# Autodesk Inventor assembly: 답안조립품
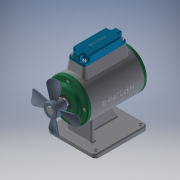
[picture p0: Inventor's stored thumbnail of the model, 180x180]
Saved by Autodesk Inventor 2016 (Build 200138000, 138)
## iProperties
Created: 2019-07
Part Number: 답안조립품
Material: 일반
Document SubType Name: Assembly
Designer: 602-01
Mass: 3420.4 g
Surface Area: 2825.58 cm^2
Volume: 1021.29 cm^3
Density: 3.34909 g/cm^3
Author: 602-01
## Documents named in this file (19)
- C:\Users\602-01\Desktop\390704V1072\답안조립품.iam
- C:\Users\602-01\Desktop\390704V1072\본체.ipt
- C:\Users\602-01\Desktop\390704V1072\베어링 6203.ipt
- C:\Users\602-01\Desktop\390704V1072\앞커버.ipt
- C:\Users\602-01\Desktop\390704V1072\오일실 17 30 8.ipt
- C:\Users\602-01\Desktop\390704V1072\축.ipt
- C:\Users\602-01\Desktop\390704V1072\키 5 x 5 x 18.ipt
- C:\Users\602-01\Desktop\390704V1072\팬날개.ipt
- 팬날개.ipt
- C:\Users\602-01\Desktop\390704V1072\볼트 M4 x 12.ipt
- C:\Users\602-01\Desktop\390704V1072\뒤커버.ipt
- C:\Users\602-01\Desktop\390704V1072\부시.ipt
- C:\Users\602-01\Desktop\390704V1072\슬라이드.ipt
- C:\Users\602-01\Desktop\390704V1072\헤더커버.ipt
- C:\Users\602-01\Desktop\390704V1072\스프링1.ipt
- C:\Users\602-01\Desktop\390704V1072\스프링2.ipt
- C:\Users\602-01\Desktop\390704V1072\스프링3.ipt
- C:\Users\602-01\Desktop\390704V1072\볼트 M4 x 16.ipt
- C:\Users\602-01\Desktop\390704V1072\멈춤나사 M4 x 5.ipt
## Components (1 placed, 1 different names)
1. 헤더커버:1
